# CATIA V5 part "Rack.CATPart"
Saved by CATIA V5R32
Part number: Part2
Bounding box of the stored display mesh (mm): x -50 to 50, y -15 to 20, z 15 to 70
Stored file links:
  D:\PROJECTS\Project 2022\CATIA V5 6R 2022\Resources\Part Files\c16_catia_v5_6r2022_prt\Rack Joint-(Fig16-57)\Rack.CATPart
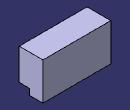
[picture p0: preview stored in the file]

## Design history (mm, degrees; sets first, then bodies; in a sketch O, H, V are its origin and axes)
Body1 (main body)
  Sketch1 on yz-plane, origin (0, 0, 0), H (0, 1, 0), V (0, 0, 1)
    line L1 (0, 15) -> (20, 15)
    point P1 (0, 15)
    reference intersected line E1 through (0, 0) direction (-1, 0) from xy-plane
    reference intersected line E3 through (0, 0) direction (0, 1) from zx-plane
    reference intersected line E4 through (0, 0) direction (-1, 0) from xy-plane
    reference intersected line E6 through (0, 0) direction (0, 1) from zx-plane
    point P3 (20, 70)
    line L2 (20, 70) -> (-15, 70)
    point P4 (-15, 70)
    reference intersected line E7 through (0, 0) direction (-1, 0) from xy-plane
    reference intersected line E9 through (0, 0) direction (0, 1) from zx-plane
    line L3 (20, 15) -> (20, 70)
    line L4 (-15, 70) -> (-15, 24)
    line L5 (-15, 24) -> (0, 24)
    point P6 (0, 24)
    line L6 (0, 15) -> (0, 24)
    distance E1 L1 = 15
    distance H L2 = 70
    distance P3 P4 = 35
    length L1 = 20
    length L6 = 9
    horizontal: L1 H, E1 H, E4 H, L2 H, E7 H, L5 H
    vertical: E3 V, E6 V, E9 V, L3 V, L4 V, L6 V
    coincidence: P1 V, P6 V
  Pad1: profile Sketch1, direction (1, 0, 0), length 50, mirrored extent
